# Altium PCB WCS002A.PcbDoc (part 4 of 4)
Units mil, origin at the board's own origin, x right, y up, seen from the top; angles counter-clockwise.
Board outline 2300 x 4058 mil, 4 copper layers (TOP, GND, PWR, BOTTOM), stack 28.8 mil thick; 311 components, 217 nets, 982 pads, 644 vias.
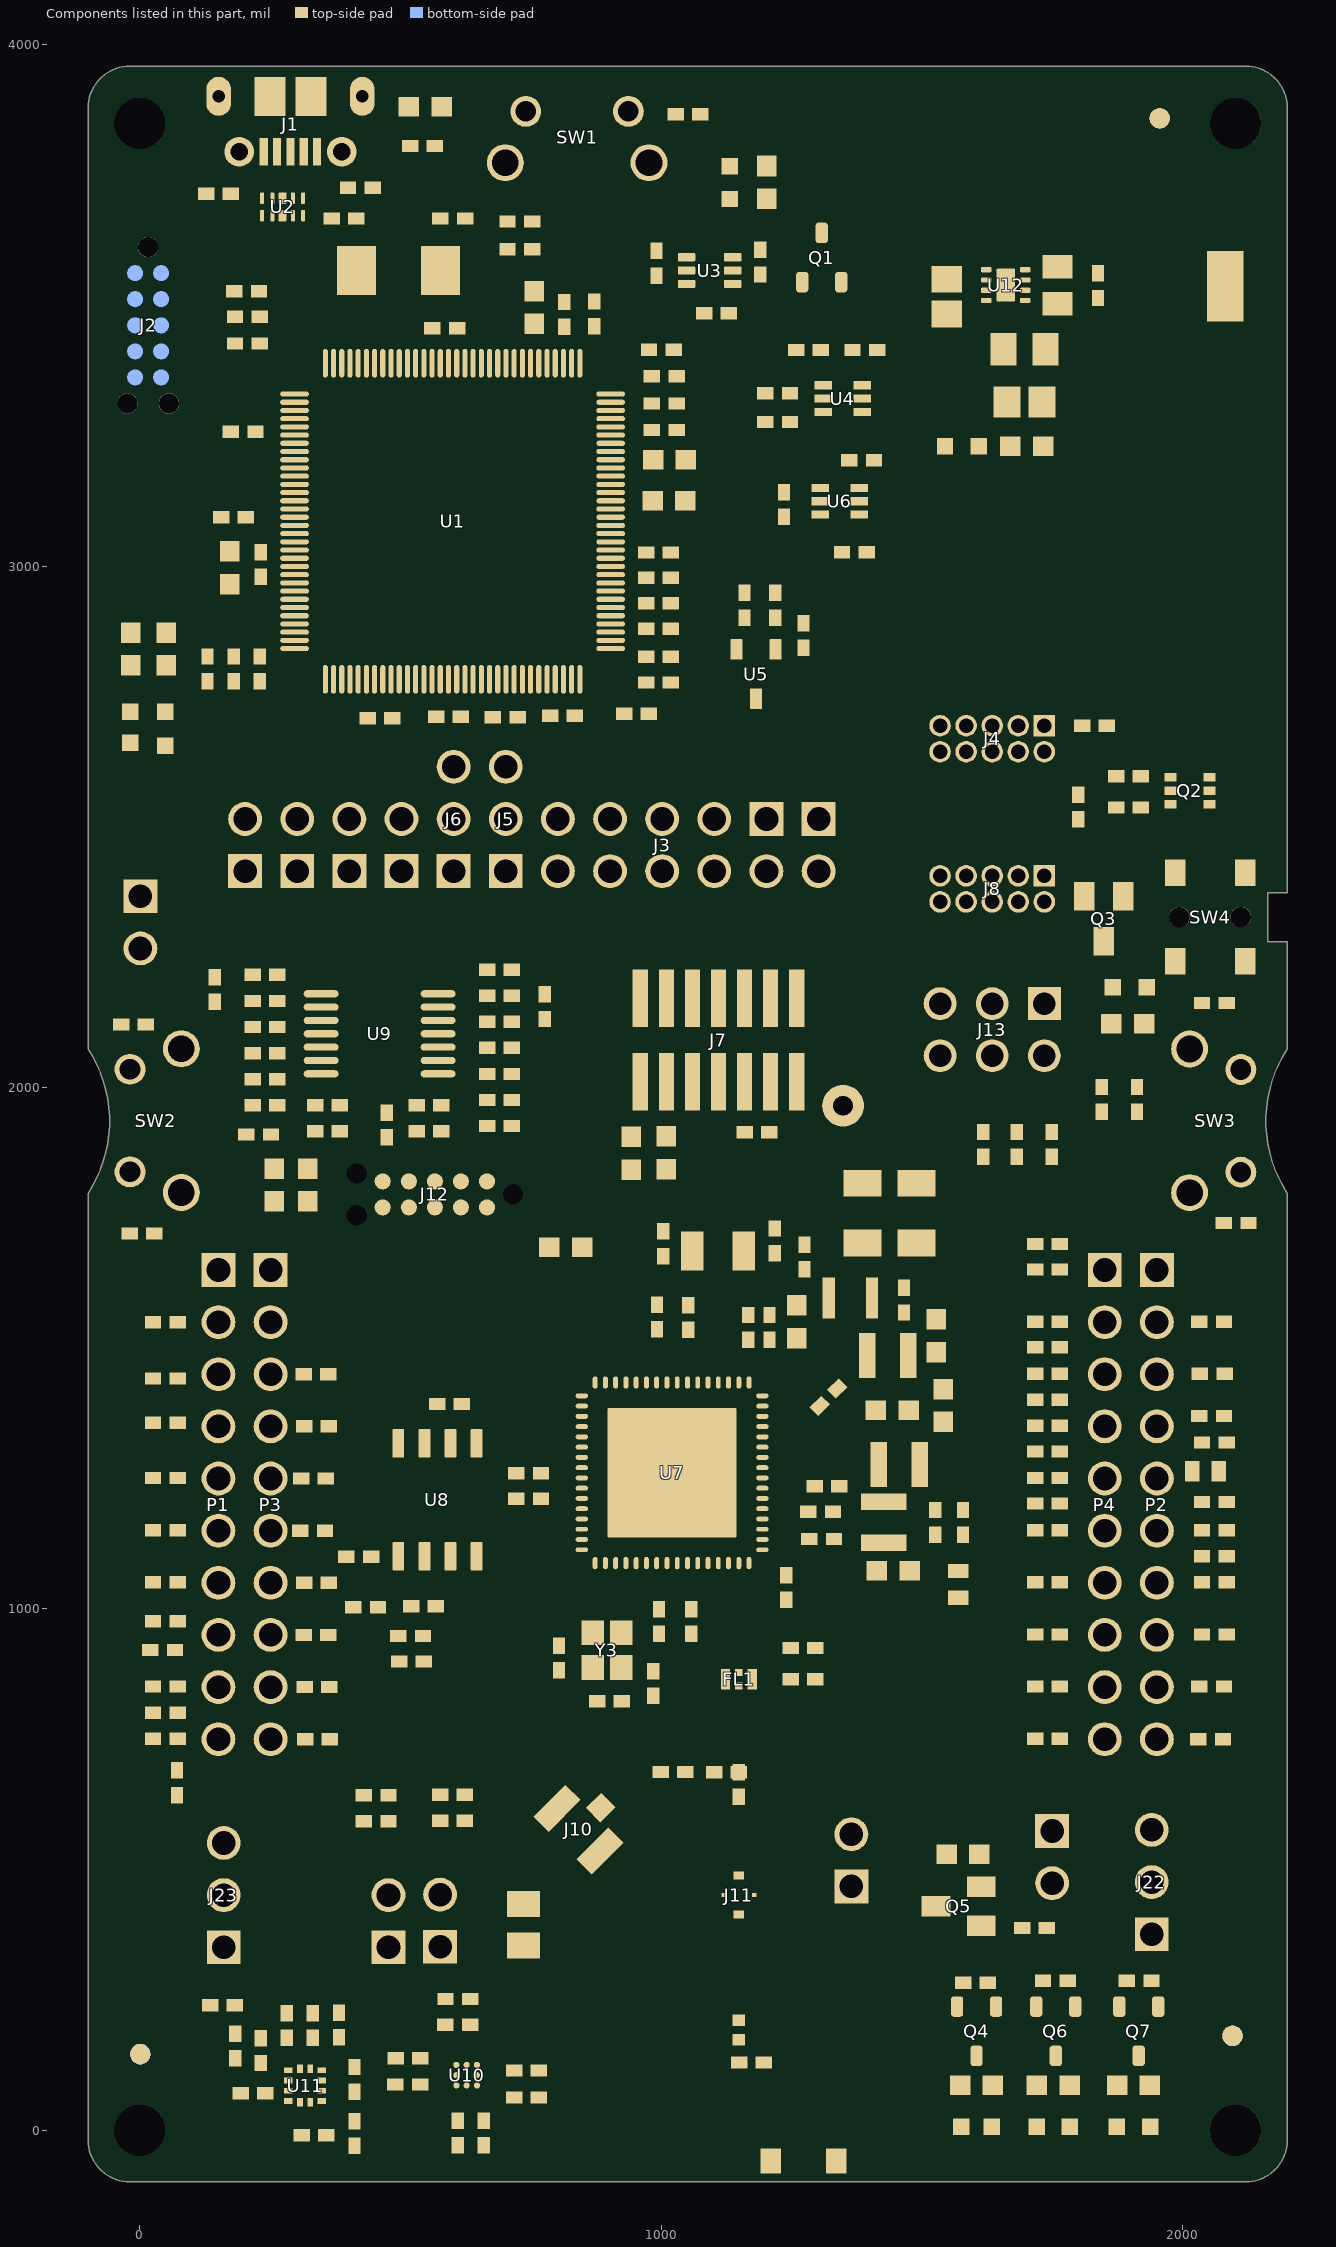
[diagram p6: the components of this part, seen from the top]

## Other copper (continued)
PWR:
  pour cut-out: 39.3,-73.7 2161.3,-73.7 2162.1,-74.5 2160.7,-74.5 2143.3,-91.9 -20.8,-91.9 -23.3,-89.4 -23.3,-87.2 -9,-72.9 -8.2,-73.7 39.24,-73.7
  pour cut-out: -75.6,1785.9 -21,1840.5 -21,2051.2 -79,2109.2 -81.8,2109.2 -91.1,2099.9 -91.1,2066.3 -64.8,2040 -64.8,1909.1 -49,1893.3 -82.21,1860.09 -82.21,1795.18 -73.7,1786.67
  pour cut-out: 2173.7,2094.5 2104.2,2025 2104.2,1823.6 2181.9,1745.9 2181.9,1805.9 2182.8,1806.8 2149,1840.6 2149,2010.3 2174,2035.3 2174,2093.8
  pour cut-out: 271,2465 271,2446 272,2445 632,2445 642.27,2455.27 634.54,2463 273,2463
  pour cut-out: -23.89,-74.21 -39.21,-74.21 -79.21,-34.21 -79.21,-5.84 -69.89,-5.84 -69.27,-10.12 -68.12,-16.12 -66.46,-21.99 -64.29,-27.7 -61.63,-33.2 -58.5,-38.44 -54.93,-43.4 -50.93,-48.02 -46.56,-52.27 -41.82,-56.13 -36.77,-59.56 -31.44,-62.54 -26.96,-64.6 -23.89,-65.88 -23.89,-74.21
  pour cut-out: 1099.37,106.14 1335.59,106.14 1335.59,-90.71 1099.37,-90.71
  pour cut-out: 1582,1506 1650,1506 1652,1504 1652,1481 1646,1475 1613,1475
  pour cut-out: 1620.4,1491.3 1620.4,1567.6 1597.79,1590.21 1597.79,1627.24 1593.32,1631.7 1572.1,1631.7 1572.1,1514.9 1595.5,1491.5 1620.3,1491.5
  pour cut-out: 109.4,1691.7 112.9,1695.2 190,1695.2 214.7,1670.5 214.7,1659.8 204.69,1649.79 113.31,1649.79 109.3,1653.8 109.4,1653.9
  pour cut-out: 709.1,2645 713.6,2640.5 725.8,2640.5 728.3,2643 728.3,2666.52 724.03,2670.79 714.19,2670.79 709.1,2665.7
  pour cut-out: 696.6,1322.3 696.6,1259.1 703.5,1252.2 708.2,1252.2 723.7,1267.7 723.7,1314.3 713,1325 709.8,1321.8 696.3,1321.8
  pour cut-out: 1292.69,3147.2 1291.14,3155 1286.72,3161.62 1280.1,3166.04 1272.3,3167.59 1264.5,3166.04 1257.88,3161.62 1253.46,3155 1251.91,3147.2 1253.46,3139.4 1257.88,3132.78 1264.5,3128.36 1272.3,3126.81 1280.1,3128.36 1286.72,3132.78 1291.14,3139.4 1292.69,3147.2
  pour cut-out: 381.29,3048.9 379.74,3056.7 375.32,3063.32 368.7,3067.74 360.9,3069.29 353.1,3067.74 346.48,3063.32 342.06,3056.7 340.51,3048.9 342.06,3041.09 346.48,3034.48 353.1,3030.06 360.9,3028.5 368.7,3030.06 375.32,3034.48 379.74,3041.09 381.29,3048.9
  pour cut-out: 1670.62,3576.07 1669.06,3583.87 1664.64,3590.49 1658.03,3594.91 1650.22,3596.46 1642.42,3594.91 1635.8,3590.49 1631.38,3583.87 1629.83,3576.07 1631.38,3568.27 1635.8,3561.65 1642.42,3557.23 1650.22,3555.68 1658.03,3557.23 1664.64,3561.65 1669.06,3568.27 1670.62,3576.07
  pour cut-out: 1683.39,3575.2 1681.84,3583 1677.42,3589.62 1670.8,3594.04 1663,3595.59 1655.2,3594.04 1648.58,3589.62 1644.16,3583 1642.61,3575.2 1644.16,3567.4 1648.58,3560.78 1655.2,3556.36 1663,3554.81 1670.8,3556.36 1677.42,3560.78 1681.84,3567.4 1683.39,3575.2
  pour cut-out: 711.58,678.76 710.03,686.56 705.61,693.18 699,697.6 691.19,699.15 683.39,697.6 676.77,693.18 672.35,686.56 670.8,678.76 672.35,670.96 676.77,664.34 683.39,659.92 691.19,658.37 699,659.92 705.61,664.34 710.03,670.96 711.58,678.76
  pour cut-out: 634.93,1221.66 633.38,1229.46 628.96,1236.08 622.34,1240.5 614.54,1242.05 606.74,1240.5 600.12,1236.08 595.7,1229.46 594.15,1221.66 595.7,1213.86 600.12,1207.24 606.74,1202.82 614.54,1201.27 622.34,1202.82 628.96,1207.24 633.38,1213.86 634.93,1221.66
  pour cut-out: 434.18,1696.79 432.63,1704.59 428.21,1711.21 421.59,1715.63 413.79,1717.18 405.98,1715.63 399.37,1711.21 394.95,1704.59 393.4,1696.79 394.95,1688.98 399.37,1682.37 405.98,1677.95 413.79,1676.4 421.59,1677.95 428.21,1682.37 432.63,1688.98 434.18,1696.79
  pour cut-out: 649.17,1696.79 647.62,1704.59 643.2,1711.21 636.58,1715.63 628.78,1717.18 620.98,1715.63 614.36,1711.21 609.94,1704.59 608.39,1696.79 609.94,1688.98 614.36,1682.37 620.98,1677.95 628.78,1676.4 636.58,1677.95 643.2,1682.37 647.62,1688.98 649.17,1696.79
  pour cut-out: 438.79,1709.9 437.24,1717.7 432.82,1724.32 426.2,1728.74 418.4,1730.29 410.6,1728.74 403.98,1724.32 399.56,1717.7 398.01,1709.9 399.56,1702.1 403.98,1695.48 410.6,1691.06 418.4,1689.51 426.2,1691.06 432.82,1695.48 437.24,1702.1 438.79,1709.9
  pour cut-out: 1006.18,1640.61 1004.63,1648.42 1000.21,1655.03 993.59,1659.45 985.79,1661.01 977.98,1659.45 971.37,1655.03 966.95,1648.42 965.4,1640.61 966.95,1632.81 971.37,1626.19 977.98,1621.77 985.79,1620.22 993.59,1621.77 1000.21,1626.19 1004.63,1632.81 1006.18,1640.61
  pour cut-out: 1235.59,1619.9 1234.04,1627.7 1229.62,1634.32 1223,1638.74 1215.2,1640.29 1207.4,1638.74 1200.78,1634.32 1196.36,1627.7 1194.81,1619.9 1196.36,1612.1 1200.78,1605.48 1207.4,1601.06 1215.2,1599.51 1223,1601.06 1229.62,1605.48 1234.04,1612.1 1235.59,1619.9
  pour cut-out: 1246.7,1603.27 1245.15,1611.07 1240.73,1617.69 1234.12,1622.11 1226.31,1623.66 1218.51,1622.11 1211.89,1617.69 1207.47,1611.07 1205.92,1603.27 1207.47,1595.47 1211.89,1588.85 1218.51,1584.43 1226.31,1582.88 1234.12,1584.43 1240.73,1588.85 1245.15,1595.47 1246.7,1603.27
  pour cut-out: 1381,1136.01 1379.45,1143.81 1375.03,1150.43 1368.41,1154.85 1360.61,1156.4 1352.8,1154.85 1346.19,1150.43 1341.77,1143.81 1340.22,1136.01 1341.77,1128.21 1346.19,1121.59 1352.8,1117.17 1360.61,1115.62 1368.41,1117.17 1375.03,1121.59 1379.45,1128.21 1381,1136.01
  pour cut-out: 1166.88,1594.79 1165.33,1602.59 1160.91,1609.21 1154.3,1613.63 1146.49,1615.18 1138.69,1613.63 1132.07,1609.21 1127.65,1602.59 1126.1,1594.79 1127.65,1586.99 1132.07,1580.37 1138.69,1575.95 1146.49,1574.4 1154.3,1575.95 1160.91,1580.37 1165.33,1586.99 1166.88,1594.79
  text ".layer_Name" at -459.21,-1181.21 h60
BOTTOM:
  pour cut-out: 39.3,-73.7 2161.3,-73.7 2162.1,-74.5 2160.7,-74.5 2143.3,-91.9 -20.8,-91.9 -23.3,-89.4 -23.3,-87.2 -9,-72.9 -8.2,-73.7 39.24,-73.7
  pour cut-out: 2173.7,2094.5 2104.2,2025 2104.2,1823.6 2181.9,1745.9 2181.9,1805.9 2182.8,1806.8 2149,1840.6 2149,2010.3 2174,2035.3 2174,2093.8
  pour cut-out: -75.6,1785.9 -21,1840.5 -21,2051.2 -79,2109.2 -81.8,2109.2 -91.1,2099.9 -91.1,2066.3 -64.8,2040 -64.8,1909.1 -49,1893.3 -82.21,1860.09 -82.21,1795.18 -73.7,1786.67
  pour cut-out: 1603,3528 1603,3468 1599,3464 1588,3464 1581,3471 1581,3493 1597,3509 1595,3511 1595,3521 1596,3521
  pour cut-out: 869,3482 927.16,3423.84 927.16,3411.09 928,3411.93 928,3450 896,3482
  pour cut-out: 1088.49,3311.38 1086.94,3319.19 1082.52,3325.8 1075.9,3330.22 1068.1,3331.78 1060.29,3330.22 1053.68,3325.8 1049.26,3319.19 1047.71,3311.38 1049.26,3303.58 1053.68,3296.96 1060.29,3292.54 1068.1,3290.99 1075.9,3292.54 1082.52,3296.96 1086.94,3303.58
  pour cut-out: 1729.79,1479.77 1729.75,1478.9 1729.64,1478.03 1729.45,1477.18 1729.18,1476.35 1728.85,1475.55 1728.45,1474.77 1727.98,1474.04 1727.45,1473.34 1726.86,1472.7 1726.22,1472.11 1725.52,1471.58 1724.79,1471.11 1724.01,1470.71 1723.21,1470.37 1722.38,1470.11 1721.52,1469.92 1720.66,1469.81 1719.79,1469.77 1718.92,1469.81 1718.05,1469.92 1717.2,1470.11 1716.37,1470.37 1715.56,1470.71 1714.79,1471.11 1714.05,1471.58 1713.36,1472.11 1712.72,1472.7 1703.63,1481.79 1696.88,1481.79 1696.88,1489.66 1699.36,1491.11 1700.6,1491.91 1701.78,1492.82 1702.87,1493.82 1703.86,1494.92 1704.76,1496.1 1705.55,1497.36 1706.23,1498.68 1706.79,1500.05 1707.23,1501.47 1707.54,1502.92 1707.73,1504.39 1707.78,1505.3 1707.84,1507.28 1712.72,1512.16 1713.36,1512.75 1714.05,1513.28 1714.79,1513.75 1715.56,1514.15 1716.37,1514.49 1717.2,1514.75 1718.05,1514.94 1718.92,1515.05 1719.79,1515.09 1720.66,1515.05 1721.52,1514.94 1722.38,1514.75 1723.21,1514.49 1724.01,1514.15 1724.79,1513.75 1725.52,1513.28 1726.21,1512.75 1726.86,1512.16 1727.45,1511.52 1727.98,1510.82 1728.45,1510.09 1728.85,1509.31 1729.18,1508.51 1729.45,1507.68 1729.64,1506.83 1729.75,1505.96 1729.79,1505.09 1729.79,1479.77
  pour cut-out: 152 vertices and 0 holes, not listed, extent 1873.24,1006.79 1928.33,1089.79
  pour cut-out: 2001.13,911.89 1987.86,911.89 1986.98,911.93 1986.12,912.04 1985.27,912.23 1984.44,912.5 1983.63,912.83 1982.86,913.23 1982.12,913.7 1981.43,914.23 1980.78,914.82 1980.2,915.46 1979.66,916.16 1979.2,916.89 1978.79,917.67 1978.46,918.47 1978.2,919.3 1978.01,920.16 1977.89,921.02 1977.86,921.89 1977.89,922.76 1978.01,923.63 1978.2,924.48 1978.46,925.31 1978.79,926.12 1979.2,926.89 1979.66,927.63 1979.97,928.04 1981.84,930.67 1983.48,933.45 1984.86,936.37 1985.99,939.39 1986.85,942.5 1987.43,945.68 1987.74,948.89 1987.76,952.12 1987.51,955.34 1986.97,958.52 1986.16,961.64 1985.08,964.69 1983.74,967.62 1982.6,969.68 1982.19,970.45 1981.84,971.25 1981.57,972.08 1981.37,972.93 1981.25,973.79 1981.2,974.66 1981.23,975.54 1981.33,976.4 1981.51,977.26 1981.76,978.09 1982.08,978.9 1982.48,979.68 1982.94,980.42 1983.46,981.12 1984.04,981.77 1984.68,982.37 1985.36,982.91 1986.09,983.39 1986.86,983.8 1987.66,984.14 1988.49,984.41 1989.34,984.61 1990.2,984.74 1991.07,984.79 1991.2,984.79 2005.34,984.79 2082.72,1062.16 2083.36,1062.75 2084.05,1063.28 2084.79,1063.75 2085.56,1064.15 2086.37,1064.49 2087.2,1064.75 2088.05,1064.94 2088.92,1065.05 2089.79,1065.09 2090.66,1065.05 2091.52,1064.94 2092.38,1064.75 2093.21,1064.49 2094.01,1064.15 2094.79,1063.75 2095.52,1063.28 2096.21,1062.75 2096.86,1062.16 2097.45,1061.52 2097.98,1060.82 2098.45,1060.09 2098.85,1059.31 2099.18,1058.51 2099.45,1057.68 2099.64,1056.83 2099.75,1055.96 2099.79,1055.09 2099.79,1010.54 2001.13,911.89
  pour cut-out: 1913.72,911.89 1887.86,911.89 1886.98,911.93 1886.12,912.04 1885.27,912.23 1884.44,912.5 1883.63,912.83 1882.86,913.23 1882.12,913.7 1881.43,914.23 1880.78,914.82 1880.2,915.46 1879.66,916.16 1879.2,916.89 1878.79,917.67 1878.46,918.47 1878.2,919.3 1878.01,920.16 1877.89,921.02 1877.86,921.89 1877.89,922.76 1878.01,923.63 1878.2,924.48 1878.46,925.31 1878.79,926.12 1879.2,926.89 1879.66,927.63 1879.97,928.04 1881.84,930.67 1883.48,933.45 1884.86,936.37 1885.99,939.39 1886.85,942.5 1887.43,945.68 1887.74,948.89 1887.76,952.12 1887.51,955.34 1886.97,958.52 1886.16,961.64 1885.08,964.69 1883.74,967.62 1882.6,969.68 1882.19,970.45 1881.84,971.25 1881.57,972.08 1881.37,972.93 1881.25,973.79 1881.2,974.66 1881.23,975.54 1881.33,976.4 1881.51,977.26 1881.76,978.09 1882.08,978.9 1882.48,979.68 1882.94,980.42 1883.46,981.12 1884.04,981.77 1884.68,982.37 1885.36,982.91 1886.09,983.39 1886.86,983.8 1887.66,984.14 1888.49,984.41 1889.34,984.61 1890.2,984.74 1891.07,984.79 1891.2,984.79 1910.38,984.79 1911.25,984.75 1912.11,984.64 1912.96,984.45 1913.8,984.18 1914.6,983.85 1915.38,983.45 1916.11,982.98 1916.8,982.45 1917.45,981.86 1918.04,981.22 1918.57,980.52 1919.04,979.79 1919.44,979.01 1919.77,978.21 1920.04,977.38 1920.22,976.52 1920.34,975.66 1920.38,974.79 1920.34,973.92 1920.22,973.05 1920.04,972.2 1919.77,971.37 1919.44,970.56 1919.04,969.79 1918.97,969.68 1917.45,966.84 1916.18,963.87 1915.17,960.8 1914.43,957.66 1913.97,954.47 1913.79,951.24 1913.89,948.02 1914.27,944.81 1914.93,941.65 1915.87,938.56 1917.06,935.56 1918.52,932.68 1920.22,929.94 1921.61,928.04 1922.11,927.33 1922.55,926.58 1922.93,925.79 1923.23,924.97 1923.46,924.13 1923.62,923.27 1923.71,922.4 1923.71,921.53 1923.64,920.66 1923.5,919.8 1923.28,918.96 1922.99,918.14 1922.62,917.34 1922.19,916.58 1921.7,915.87 1921.14,915.19 1920.53,914.57 1919.87,914.01 1919.16,913.5 1918.4,913.06 1917.62,912.68 1916.8,912.38 1915.96,912.15 1915.1,911.99 1914.23,911.91 1913.72,911.89
  pour cut-out: 1451.44,1729.57 1452.03,1728.93 1452.57,1728.24 1453.03,1727.5 1453.44,1726.73 1453.77,1725.92 1454.03,1725.09 1454.22,1724.24 1454.34,1723.37 1454.37,1722.5 1454.34,1721.63 1454.22,1720.77 1454.03,1719.91 1453.77,1719.08 1453.44,1718.28 1453.03,1717.5 1452.57,1716.77 1452.03,1716.07 1451.44,1715.43 1450.8,1714.84 1450.11,1714.31 1449.37,1713.84 1448.6,1713.44 1447.79,1713.11 1446.96,1712.84 1446.11,1712.65 1445.25,1712.54 1444.37,1712.5 862.2,1712.5 861.33,1712.54 860.46,1712.65 859.61,1712.84 858.78,1713.11 857.97,1713.44 857.2,1713.84 856.47,1714.31 855.77,1714.84 855.13,1715.43 854.54,1716.07 854.01,1716.77 853.54,1717.5 853.14,1718.28 852.8,1719.08 852.54,1719.91 852.35,1720.77 852.24,1721.63 852.2,1722.5 852.24,1723.37 852.35,1724.24 852.54,1725.09 852.8,1725.92 853.14,1726.73 853.54,1727.5 854.01,1728.24 854.54,1728.93 855.13,1729.57 860.34,1734.79 1446.23,1734.79 1451.44,1729.57
  pour cut-out: 1596.23,816.79 1208.52,816.79 1207.65,816.83 1206.78,816.94 1205.93,817.13 1205.1,817.39 1204.29,817.72 1203.52,818.13 1202.79,818.6 1202.09,819.13 1201.45,819.72 1200.86,820.36 1200.33,821.05 1199.86,821.79 1199.46,822.56 1199.12,823.37 1198.86,824.2 1198.67,825.05 1198.56,825.92 1198.52,826.79 1198.56,827.66 1198.67,828.52 1198.71,828.73 1198.94,830.2 1199.03,831.68 1199.03,831.75 1199.09,832.62 1199.21,833.48 1199.42,834.33 1199.69,835.16 1200.04,835.96 1200.46,836.73 1200.94,837.46 1201.48,838.14 1202.08,838.77 1202.73,839.35 1203.44,839.87 1204.18,840.33 1204.96,840.72 1205.77,841.04 1206.61,841.28 1207.46,841.46 1208.33,841.56 1209.03,841.58 1596.88,841.58 1597.76,841.54 1598.62,841.43 1599.47,841.24 1600.3,840.98 1601.11,840.65 1601.88,840.24 1602.62,839.77 1603.31,839.24 1603.95,838.65 1604.54,838.01 1605.08,837.32 1605.54,836.58 1605.95,835.81 1606.28,835 1606.54,834.17 1606.73,833.32 1606.85,832.45 1606.88,831.58 1606.85,830.71 1606.73,829.85 1606.54,828.99 1606.28,828.16 1605.95,827.36 1605.54,826.58 1605.08,825.85 1604.54,825.15 1603.95,824.51 1596.23,816.79
  pour cut-out: 935.79,741.79 1137.04,741.79 1163.04,767.79 1125.04,805.79 926.79,805.79 909.79,788.79 935.79,762.79
  pour cut-out: 1380.76,1134.37 1379.21,1142.17 1374.79,1148.79 1368.17,1153.21 1360.37,1154.76 1352.56,1153.21 1345.95,1148.79 1341.53,1142.17 1339.98,1134.37 1341.53,1126.56 1345.95,1119.95 1352.56,1115.53 1360.37,1113.98 1368.17,1115.53 1374.79,1119.95 1379.21,1126.56 1380.76,1134.37
  pour cut-out: 1398.18,1249.79 1396.63,1257.59 1392.21,1264.21 1385.59,1268.63 1377.79,1270.18 1369.98,1268.63 1363.37,1264.21 1358.95,1257.59 1357.4,1249.79 1358.95,1241.98 1363.37,1235.37 1369.98,1230.95 1377.79,1229.4 1385.59,1230.95 1392.21,1235.37 1396.63,1241.98
  pour cut-out: 1381.55,1187.68 1380,1195.48 1375.58,1202.1 1368.96,1206.52 1361.16,1208.07 1353.35,1206.52 1346.74,1202.1 1342.32,1195.48 1340.77,1187.68 1342.32,1179.87 1346.74,1173.26 1353.35,1168.84 1361.16,1167.28 1368.96,1168.84 1375.58,1173.26 1380,1179.87
  pour cut-out: 596.79,1359.79 596.79,1537.79 809.79,1750.79 1575.79,1750.79 1646.79,1679.79 1646.79,1550.79 1616.79,1520.79 823.79,1520.79 661.79,1358.79 594.79,1358.79
  pour cut-out: 732.79,786.79 1627.79,786.79 1633.79,792.79 1633.79,1108.79 1604.79,1137.79 1271.08,1137.79 1172.67,1039.38 835.19,1039.38 770.79,1103.79 770.79,1227.79 674.79,1323.79 482.79,1323.79 454.79,1295.79 454.79,1054.79 456.79,1052.79 562.79,1052.79 665.79,949.79 665.79,853.79
  pour cut-out: 1211.55,767.68 1210,775.48 1205.58,782.1 1198.96,786.52 1191.16,788.07 1183.35,786.52 1176.74,782.1 1172.32,775.48 1170.77,767.68 1172.32,759.87 1176.74,753.26 1183.35,748.84 1191.16,747.28 1198.96,748.84 1205.58,753.26 1210,759.87 1211.55,767.68
  pour cut-out: 1129.42,726.68 1127.87,734.48 1123.45,741.1 1116.83,745.52 1109.03,747.07 1101.23,745.52 1094.61,741.1 1090.19,734.48 1088.64,726.68 1090.19,718.87 1094.61,712.26 1101.23,707.84 1109.03,706.28 1116.83,707.84 1123.45,712.26 1127.87,718.87 1129.42,726.68
  pour cut-out: 1079.42,727.68 1077.87,735.48 1073.45,742.1 1066.83,746.52 1059.03,748.07 1051.23,746.52 1044.61,742.1 1040.19,735.48 1038.64,727.68 1040.19,719.87 1044.61,713.26 1051.23,708.84 1059.03,707.28 1066.83,708.84 1073.45,713.26 1077.87,719.87 1079.42,727.68
  pour cut-out: 1038.42,725.68 1036.87,733.48 1032.45,740.1 1025.83,744.52 1018.03,746.07 1010.23,744.52 1003.61,740.1 999.19,733.48 997.64,725.68 999.19,717.87 1003.61,711.26 1010.23,706.84 1018.03,705.28 1025.83,706.84 1032.45,711.26 1036.87,717.87 1038.42,725.68
  pour cut-out: 1099.37,106.14 1335.59,106.14 1335.59,-90.71 1099.37,-90.71
  pour cut-out: 1005.38,1819.54 1052.04,1819.54 1055.79,1815.79 1055.79,1801.79 1038.79,1784.79 1000.79,1784.79 987.79,1797.79 987.79,1801.94
  text ".layer_Name" at -465.21,-1173.21 h60

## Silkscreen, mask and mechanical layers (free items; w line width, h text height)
DETAILS:
  drawing of 7067 lines, arcs and shapes, not listed
  text "J1" at 78.79,3878.79 h30
  text "L2" at 84,3741 h30
  text "RESET" at 1086.21,3688.79 h30 r90
  text "RESET" at 785.79,3680.79 h30
  text "U3" at 1634.7,3602.6 h30
  text "GND" at 2019,3498.71 h30 r90
  text "3V3" at 1508,3271 h30
  text "CC3220" at 1709.5,3101.9 h120
  text "CAUTION" at -77.1,3030 h30
  text "LaunchPad" at 1708.5,3014.1 h120
  text "HOT" at -22.6,2981.9 h30
  text "Rev-A" at 1707.4,2946.3 h80
  text "SURFACE" at -80.6,2939.3 h30
  text "XDS110" at 1509.1,2841.5 h30
  text "OUT" at 1512.3,2789.6 h30
  text "VSENSE" at 1315,2589 h30 r90
  text "JTAG IN" at 1524.79,2496.79 h30
  text "FRST" at 1969.2,2465.7 h30
  text "TX" at 724,2297.14 h30 r90
  text "RX" at 623,2294 h30 r90
  text "5V" at 322.4,2272.7 h30 r90
  text "BRD" at 513.79,2267.29 h30 r90
  text "RST" at 821.79,2267.29 h30 r90
  text "TMS" at 928,2268 h30 r90
  text "TCK" at 1026.79,2267.58 h30 r90
  text "TDI" at 1127.79,2267.29 h30 r90
  text "BRD" at 1322.79,2267.29 h30 r90
  text "TDO" at 1233.79,2265.72 h30 r90
  text "GND" at 221.8,2252.3 h30 r90
  text "VBAT" at 421.7,2228 h30 r90
  text "OPAMP EN" at 108.6,2209 h30 r90
  text "J13" at 1398.6,2197.8 h30
  text "SOP" at 1466.1,2060.4 h40 r90
  text "ET POD" at 916.79,1997.79 h30 r90
  text "0" at 1729.39,1997.49 h40 r180
  text "1" at 1610.39,1955.49 h40
  text "2" at 1524.39,1954.49 h40
  text "(P15)" at 1850.9,1816.8 h30
  text "(P4)" at 137.79,1772.79 h30
  text "P4" at 1797.79,1713.79 h40
  text "P2" at 1977.9,1713.8 h40
  text "P1" at 79.79,1701.79 h40
  text "P3" at 277.79,1701.79 h40
  text "1" at 157.79,1700.79 h35
  text "21" at 207.79,1700.79 h35
  text "40" at 1858.79,1691.79 h30
  text "20" at 1916.79,1691.79 h30
  text "*" at 1678.9,1655.2 h30
  text "P02" at 1606.19,1630.79 h30
  text "*" at 1671.4,1559.4 h30
  text "*" at -16.21,1549.79 h30
  text "P18" at 2107.4,1535.2 h30
  text "P01" at 1606.19,1530.79 h30
  text "P58" at -88.91,1514.19 h30
  text "U13" at 787.79,1474.79 h35
  text "*" at 1675.6,1456.8 h30
  text "P57" at 388.8,1435.3 h30
  text "P08" at 2107.5,1433.2 h30
  text "P17" at 1606.19,1430.79 h30
  text "P04" at -89.21,1428.79 h30
  text "*" at 1674.2,1354.5 h30
  text "P45" at 2106.1,1348.7 h30
  text "P60" at 390.9,1341.1 h30
  text "P03" at -91.1,1337.6 h30
  text "P64" at 1606.19,1329.79 h30
  text "*" at 1663.9,1271.1 h30
  text "P61" at -84.1,1241.1 h30
  text "RST" at 2109.9,1240.5 h30
  text "P58" at 386.1,1237.6 h30
  text "P21" at 1606.19,1234.79 h30
  text "*" at 1666.5,1169 h30
  text "*" at -28,1158 h30
  text "P59" at 380.2,1138.1 h30
  text "P07" at 2108.9,1136 h30
  text "P18" at 1606.19,1134.79 h30
  text "P59" at -89.2,1125.2 h30
  text "*" at 1677.8,1060.1 h30
  text "P05" at -89.21,1040.79 h30
  text "P06" at 2111.7,1035.2 h30
  text "P63" at 390.9,1033.3 h30
  text "P62" at 1608.5,1033.8 h30
  text "*" at 1666.3,967.5 h30
  text "P62" at -89.4,952.9 h30
  text "P21" at 2113.3,934.6 h30
  text "P53" at 395,932.6 h30
  text "P60" at 1606.19,932.79 h30
  text "P01" at -89.21,840.79 h30
  text "P55" at 2104.7,834.5 h30
  text "P64" at 391.9,830 h30
  text "P16" at 1606.19,827.79 h30
  text "P02" at -89.21,740.79 h30
  text "P17" at 1606.19,738.79 h30
  text "P50" at 392.8,732.4 h30
  text "P15" at 2106.5,732.9 h30
  text "30" at 227.96,667.79 h35
  text "11" at 1929.61,667.78 h35
  text "10" at 125.79,666.79 h35
  text "31" at 1827.44,666.78 h35
  text "RF" at 705.6,502 h30
  text "RF" at 1004.79,466.79 h30
  text "RST PU" at 1682.79,458.79 h30 r90
  text "LED EN" at 1283.6,449.3 h30 r90
  text "Q2" at 1434.6,356.2 h30
  text "(SCL)" at 389.79,325.79 h30 r90
  text "(SDA)" at 671.79,313.79 h30 r90
  text "D8->P02" at 1279.7,246.4 h30
  text "Q5" at 2019,208.9 h30 r90
  text "D9->P01" at 1279.79,194.79 h30
  text "Q4" at 1850.79,194.79 h30 r90
  text "Q3" at 1543.79,192.79 h30 r90
  text "TEMP" at 671.79,153.79 h30
  text "D10->P64" at 1277.79,143.79 h30
  text "SENSORS" at 121.79,-6.21 h30 r90
  text "ACC" at 152.79,-63.21 h30
  text "SILKSCREEN TOP" at -415.75,-1159.26 h60
QRCODE:
  drawing of 11592 lines, arcs and shapes, not listed
  text "CC3220x-LAUNCHXL" at 1252,3290.5 h125
  text "Development Kit" at 1248.2,3176.8 h125
  text "www.ti.com/launchpad" at 1579.5,2925.2 h125
  text "XDS110 OUT" at 1804.9,2733.8 h70
  text "VSENSE" at 1289,2579 h50 r270
  text "JTAG IN" at 1755,2457 h70
  text "OPAMP EN" at 72.8,2226 h50 r270
  text "GND" at 144.5,2224.5 h50 r270
  text "BRD" at 449.2,2224.9 h50 r270
  text "RX" at 549.3,2224.7 h50 r270
  text "TX" at 649.4,2224.7 h50 r270
  text "TCK" at 952.9,2224.4 h50 r270
  text "TDI" at 1051.1,2225.1 h50 r270
  text "TDO" at 1149.8,2224.5 h50 r270
  text "5V" at 249.6,2223.8 h50 r270
  text "VBAT" at 349,2224.1 h50 r270
  text "RST" at 753.1,2224.1 h50 r270
  text "TMS" at 851.8,2223.6 h50 r270
  text "BRD" at 1252.9,2224 h50 r270
  text "SOP" at 1710.2,2214.32 h70
  text "SOP (2:0)" at 1178.4,2005.6 h40
  text "100  :  FLASH" at 1176.4,1945.6 h30
  text "000  :  4W JTAG" at 1175.4,1886.6 h30
  text "001  :  2W SWD" at 1178.4,1833.6 h30
  text "010  :  FLASH/FUNC" at 1176.4,1781.6 h30
  text "1" at 167,1728 h35
  text "21" at 266,1728 h35
  text "40" at 1878,1728 h35
  text "20" at 1969,1728 h35
  text "P02(NC)" at 1777.79,1632.79 h35
  text "P18" at 2102.79,1537.79 h35
  text "P01(NC)" at 1777.79,1532.79 h35
  text "P58(NC)" at 86.1,1530.4 h31
  text "P08" at 2105.79,1435.79 h35
  text "P57" at 403.8,1432.4 h35
  text "P17(NC)" at 1777.79,1432.79 h35
  text "P04" at 80,1427.79 h35
  text "P60" at 400,1341.7 h35
  text "P45" at 2106.79,1334.79 h35
  text "P64(NC)" at 1777.79,1331.79 h35
  text "P03" at 80,1327.79 h35
  text "P58" at 401.5,1244.1 h35
  text "P21(NC)" at 1777.79,1234.79 h35
  text "RST" at 2099.79,1234.79 h35
  text "P61" at 80,1227.79 h35
  text "P07" at 2103.7,1137.4 h35
  text "P59" at 400,1133.5 h35
  text "P18(NC)" at 1777.79,1133.79 h35
  text "P59(NC)" at 86.2,1128.1 h33
  text "P62(NC)" at 1777.79,1037.79 h35
  text "P06" at 2096.79,1036.79 h35
  text "P05" at 80,1027.79 h35
  text "P63" at 399.2,1026 h35
  text "P21" at 2100.79,934.79 h35
  text "P60(NC)" at 1777.79,933.79 h35
  text "P62" at 80,927.79 h35
  text "P53" at 405.1,919.8 h35
  text "P64" at 404.9,835.8 h35
  text "P55" at 2100.79,834.79 h35
  text "P16(NC)" at 1777.79,830.79 h35
  text "P01" at 80,827.79 h35
  text "P50" at 399.7,735.8 h35
  text "P15" at 2100.79,734.79 h35
  text "P17(NC)" at 1777,734 h35
  text "P02" at 80,727.79 h35
  text "30" at 272.39,635.79 h35
  text "11" at 1963.2,635.8 h35
  text "31" at 1869.3,635 h35
  text "10" at 166.39,633.79 h35
  text "LED EN" at 1251.7,450.6 h30 r270
  text "WCS002A" at 1032.9,249.3 h50
  text "not FCC approved for resale." at 1034.19,84.19 h40
  text "SILKSCREEN BOTTOM" at -415.75,-1159.26 h60
Top Paste:
  text ".layer_Name" at -406.21,-1149.21 h60
Bottom Paste:
  text ".layer_Name" at -446.21,-1143.21 h60
Top Solder:
  region: 1131.07,438.19 1122.02,429.13 1103.51,429.13 1103.51,472.44 1122.02,472.44 1131.07,463.39
  region: 1166.5,463.39 1175.56,472.44 1194.06,472.44 1194.06,429.13 1175.56,429.13 1166.5,438.19
  text ".layer_Name" at -415.21,-1139.21 h60
Bottom Solder:
  text ".layer_Name" at -403.21,-1146.21 h60
M1  Board Outline:
  the board outline again, w10
M2 Board Dimensions:
  drawing of 35 lines, arcs and shapes, not listed
  text "2 PLACES" at -655.21,1985 h60
  text "4 PLACES" at 1480.79,-337 h60
M3 3D STEP Top:
  pour cut-out: 1580.79,1720.79 1580.79,960.79 1155.79,960.79 1155.79,990.79 1120.79,1025.79 1035.79,1025.79 1000.79,990.79 1000.79,910.79 935.79,910.79 935.79,805.79 925.79,795.79 655.79,795.79 655.79,1720.79 1580.79,1720.79
AST:
  circle w6: c1362.2,399 r7.21
  circle w6: c1.7,2440.1 r7.21
  circle w10: c1236.6,3528.4 r8.25
  circle w10: c993.8,3910.8 r4
  circle w10: c2112.8,1779.6 r4
  circle w10: c-10.3,2086.6 r4
  circle w6: c407.49,299.59 r10
  circle w6: c642.69,302.79 r10
  circle w10: c1942.2,2450.2 r8.06
  circle w6: c78.79,346.79 r10
  circle w6: c1690.79,311.79 r7.21
  circle w6: c1074.32,1668.79 r4.47
  circle w6: c341.79,3736.79 r7.21
  circle w6: c205,2339 r7.21
  circle w6: c305,2339 r7.21
  circle w6: c405,2339 r7.21
  circle w6: c505,2339 r7.21
  circle w6: c605,2339 r7.21
  circle w6: c705,2339 r7.21
  circle w6: c1204,2596 r7.21
  circle w6: c1302,2597 r7.21
  circle w6: c1304,2190 r7.21
  circle w6: c1752.4,2467.5 r7.21
  circle w6: c1772,2754 r7.21
  circle w6: c1670,241 r7.21
  circle w6: c1826,242 r7.21
  circle w6: c1987,242 r7.21
  circle w6: c1623,346 r7.21
  circle w6: c1819,590 r7.21
  circle w10: c1219.19,2798.39 r8.06
  circle w6: c1074.32,1668.79 r4.47
  circle w6: c879.2,671.8 r6.71
  circle w6: c1869,379 r7.21
  circle w6: c78.79,346.79 r10
  circle w10: c352,3588 r8.25
  circle w10: c1958.7,2632.2 r8.06
  lines w10: -1273.71,-1222.38 5326.29,-1222.38 ; -1273.71,-1019.05 5328.29,-1019.05 ; -1273.71,-815.71 -1273.71,-1425.71 2731.29,-1425.71 5328.29,-1425.71 5328.29,-815.71 -1273.21,-815.71 -1273.21,-1425.71 302.29,-1425.71 ; 1191.29,-1425.71 1191.29,-815.71 ; 1893.38,2422.16 ccw(c1886.1,2418.7) 1894.16,2418.7 ; 2458.29,-1019.05 2458.29,-815.71 ; 3298.29,-1019.05 3298.29,-815.71 ; 3920.29,-1432.21 3920.29,-1229.38
  text "J1" at 264.7,3857.6 h30
  text "L2" at 130.7,3702.1 h24
  text "J15" at 1594.5,2096.7 h30
  text "J25" at 511.8,1776.3 h30
  text "REFER SPECIAL" at 353.5,1686.5 h30
  text "ASSEMBLY NOTE" at 324.3,1633.8 h30
  text "Special Assembly Note: Please provide a insulating tape on the J25 (DNP) pads to avoid the paste and led on them while soldering the other parts." at 176.79,-493.91 h35
  text "COMPONENTS MARKED 'DNP' SHOULD NOT BE POPULATED." at 171.79,-610.71 h35
  text "ASSEMBLY VARIANT:" at 171.29,-726.21 h35
  text ".VariantName" at 1207.29,-726.21 h35
  text "PCB VIEWED FROM TOP SIDE" at -1210.21,-947.88 h35
  text "BOARD #:" at 1266.29,-947.88 h35
  text ".PRJ_Number" at 1811.79,-947.88 h35
  text "REV:" at 2656.29,-947.88 h35
  text ".PCB_Rev" at 2947.79,-947.88 h35
  text "SVN REV:" at 3494.29,-947.88 h35
  text ".VersionControl_RevNumber" at 4000.29,-947.88 h35
  text "IGNORE ->" at -1210.21,-1150.71 h35
  text ".Layer_Name" at -427.71,-1150.21 h35
  text "PLOT NAME =" at -1210.21,-1356.55 h35
  text ".plot_File_Name" at -404.71,-1356.55 h35
  text "GENERATED    :" at 1268.29,-1356.55 h35
  text ".Print_Date" at 2137.79,-1356.55 h35
  text ".Print_Time" at 2866.79,-1356.55 h35
  text "TEXAS INSTRUMENTS" at 4131.29,-1356.55 h35
ASB:
  lines w10: -1274.21,-1019.55 5327.79,-1019.55 ; -1272.21,-1222.88 5327.79,-1222.88 ; 133.79,-1432.71 133.79,-1229.88 ; 755.79,-1019.55 755.79,-816.21 ; 1595.79,-1019.55 1595.79,-816.21 ; 2862.79,-1426.21 2862.79,-816.21 ; 3751.79,-1426.21 5327.29,-1426.21 5327.29,-816.21 -1274.21,-816.21 -1274.21,-1426.21 1322.79,-1426.21 5327.79,-1426.21 5327.79,-816.21
  text "COMPONENTS MARKED 'DNP' SHOULD NOT BE POPULATED." at 5120.29,-610.21 h35
  text ".VariantName" at 4076.29,-726.21 h35
  text "ASSEMBLY VARIANT:" at 5115.29,-726.21 h35
  text ".VersionControl_RevNumber" at 53.79,-948.38 h35
  text "SVN REV:" at 559.79,-948.38 h35
  text ".PCB_Rev" at 1106.29,-948.38 h35
  text "REV:" at 1397.79,-948.38 h35
  text ".PRJ_Number" at 2242.29,-948.38 h35
  text "BOARD #:" at 2787.79,-948.38 h35
  text "PCB VIEWED FROM BOTTOM SIDE" at 5264.29,-948.38 h35
  text "IGNORE ->" at 1566.14,-1150.71 h35
  text ".Layer_Name" at 1226.79,-1153.21 h35
  text "TEXAS INSTRUMENTS" at -77.21,-1357.05 h35
  text ".Print_Time" at 1187.29,-1357.05 h35
  text ".Print_Date" at 1916.29,-1357.05 h35
  text "GENERATED    :" at 2785.79,-1357.05 h35
  text ".plot_File_Name" at 4458.79,-1357.05 h35
  text "PLOT NAME =" at 5264.29,-1357.05 h35
M9 Title Sheet:
  drawing of 56 lines, arcs and shapes, not listed
  text "1" at -252.91,7735.73 h70
  text "2" at 2242.75,7735.73 h70
  text "3" at 4732.1,7735.73 h70
  text "4" at 7238.77,7735.73 h70
  text "5" at 9737.75,7735.73 h70
  text "6" at 12242.75,7735.73 h70
  text "A" at -1409.25,6592.73 h70
  text "A" at 13390.75,6592.73 h70
  text "B" at -1409.25,4212.73 h70
  text "B" at 13390.75,4212.73 h70
  text "C" at -1409.25,1837.73 h70
  text "C" at 13390.75,1837.73 h70
  text "PROJECT TITLE:" at 10350.75,-23.27 h45
  text ".PRJ_Title" at 10400.75,-156.6 h70
  text "DESIGNED FOR:" at 10350.75,-324.27 h45
  text ".PRJ_Customer" at 10400.75,-464.27 h70
  text "D" at -1409.25,-532.27 h70
  text "D" at 13390.75,-532.27 h70
  text "FILE NAME:" at 10350.75,-624.27 h45
  text ".PCB_File_Name_No_Path" at 10400.75,-744.27 h70
  text "Texas Instruments (TI) and/or its licensors do not warrant the accuracy or completeness of this specification" at 5381.25,-906.11 h45
  text "ENGINEER:" at 10350.75,-914.27 h45
  text "LAYOUT BY:" at 11855.75,-914.27 h45
  text "or any information contained therein. TI and/or its licensors do not warrant that this design will meet" at 5336.27,-1018.77 h45
  text ".PRJ_Engineer" at 10400.75,-1069.26 h70
  text ".PCB_Layout" at 11906.25,-1069.26 h70
  text "the specifications, will be suitable for your application or fit for any particular purpose, or will operate in" at 5336.27,-1131.44 h45
  text "ALTIUM DESIGNER VERSION:" at 11855.75,-1224.27 h45
  text "an implementation. TI and/or its licensors do not warrant that the design is production worthy. You should" at 5336.27,-1244.1 h45
  text "completely validate and test your design implementation to confirm the system functionality for your application." at 5381.25,-1356.77 h45
  text ".print_Scale" at 10400.75,-1357.6 h70
  text ".Application_BuildNumber" at 11906.25,-1357.6 h70
  text "1" at -252.91,-1564.27 h70
  text "2" at 2242.75,-1564.27 h70
  text "3" at 4732.1,-1564.27 h70
  text "4" at 7238.77,-1564.27 h70
  text "5" at 9737.75,-1564.27 h70
  text "6" at 12242.75,-1564.27 h70
M10 Fab Notes:
  drawing of 201 lines, arcs and shapes, not listed
  text "DESIGN INFORMATION" at 11388.27,6144.23 h60
  text "MIN. TRACK WIDTH:" at 10743.71,5964.23 h60
  text "MIL" at 11994.71,5964.23 h60
  text "6" at 11835.79,5962.79 h60
  text "MIN. CLEARANCE:" at 10743.71,5832.23 h60
  text "MIL" at 11994.71,5832.23 h60
  text "5.9" at 11777.79,5820.79 h60
  text "MIN. VIA PAD SIZE:" at 10743.71,5700.23 h60
  text "18" at 11809.97,5700.23 h60
  text "MIL" at 11994.71,5700.23 h60
  text "EXTERNAL" at 12289,5560 h60
  text "0.10668mm (4.2MIL)" at 11438.71,5558.52 h60
  text "MINIMUM ANNULAR RING" at 10414.48,5554.23 h60
  text "PER" at 10614.48,5436.23 h60
  text "IPC-D-275 CLASS 2 LEVEL C" at 10834.48,5436.23 h60
  text "MIL, HOLES" at 12322.71,5323.94 h60
  text "+/-" at 11930.25,5323.23 h60
  text "+/-" at 12784.25,5323.23 h60
  text "REGISTRATION TOLERANCES:" at 10414.48,5318.23 h60
  text "METAL" at 11614.25,5318.23 h60
  text "5" at 12190.46,5318.23 h60
  text "3" at 13023.46,5318.23 h60
  text "MIL" at 13139.71,5318.23 h60
  text "MATERIAL:" at 10339.71,5108.77 h60
  text "FR-4 High Tg" at 11326.16,4968.44 h60
  text "FR-408" at 10760.72,4959.87 h60
  text "X" at 11172.71,4959.87 h60
  text "OTHER" at 12248.71,4959.87 h60
  text "1.4mm+/-10%" at 12612.25,4799.23 h60
  text "62 MIL (1.6mm) +/-10%" at 11080.82,4797.15 h60
  text "THICKNESS:" at 10414.48,4792.87 h60
  text "X" at 12247.65,4792.87 h60
  text "OTHER" at 12345.71,4792.87 h60
  text "TOLERANCE:" at 10414.48,4634.87 h60
  text "X" at 11253.79,4634.87 h60
  text "ANSI IPC-6012 TYPE 3 CLASS 2" at 11440.73,4634.87 h60
  text "OTHER +/-" at 11440.71,4478.87 h60
  text "BOW & TWIST:" at 10414.48,4321.87 h60
  text "X" at 11253.79,4321.87 h60
  text "ANSI IPC-6012 TYPE 3 CLASS 2" at 11440.73,4321.87 h60
  text "OTHER +/-" at 11440.71,4163.36 h60
  text "COPPER THICKNESS (FINISHED):" at 10393.25,3906.93 h60
  text "1.4MIL (1oz)" at 12645.25,3759.21 h60
  text "INNER SIGNAL:" at 11833.17,3754.93 h60
  text "X" at 12518.21,3754.93 h60
  text "1.4MIL (1oz)" at 11273.25,3754.21 h60
  text "OUTER:" at 10750.25,3749.93 h60
  text "X" at 11144.79,3749.29 h60
  text "DRILLING:" at 10339.71,3489.87 h60
  text "REFERENCE:" at 10414.48,3372.87 h60
  text "X" at 11062.71,3372.87 h60
  text "AS SHOWN" at 11249.71,3372.87 h60
  text "X" at 11963.71,3372.87 h60
  text "NC_DRILL FILES" at 12100.71,3372.87 h60
  text "PTH MIN COPPER THICKNESS:" at 10414.48,3214.87 h60
  text "X" at 11764.71,3214.87 h60
  text "1MIL" at 11901.71,3214.87 h60
  text "OTHER" at 12398.71,3214.87 h60
  text "BOARD FINISH:" at 10339.71,3055.87 h60
  text "SILKSCREEN:" at 10494.94,2937.87 h60
  text "X" at 11443.71,2937.87 h60
  text "TOP" at 11569.71,2937.87 h60
  text "X" at 11953.71,2937.87 h60
  text "BOTTOM" at 12080.71,2937.87 h60
  text "SILKSCREEN COLOR:" at 10494.94,2770.87 h60
  text "X" at 11442.67,2770.87 h60
  text "WHITE" at 11569.71,2770.87 h60
  text "OTHER" at 12080.71,2770.87 h60
  text "SOLDER RESIST COLOR:" at 10494.94,2600.87 h60
  text "X" at 12167.68,2446.67 h60
  text "GREEN" at 11189.71,2441.67 h60
  text "BLUE" at 11780.71,2441.67 h60
  text "OTHER" at 12318.71,2441.67 h60
  text "RED" at 12708.71,2436.67 h60
  text "IMMERSION GOLD (ENIG)" at 11400.71,2253.15 h60
  text "ENEPIG" at 12738.25,2249.87 h60
  text "SURFACE FINISH:" at 10339.71,2248.87 h60
  text "X" at 11213.77,2248.87 h60
  text "IMM. TIN/SILVER OR EQUIV" at 10669.25,2091.87 h60
  text "OTHER" at 12100.71,2091.87 h60
  text "ARRAY/PANEL:" at 10339.71,1912.87 h60
  text "CUT AND TRIM PER MECH LAYER 1" at 11400.72,1908.58 h60
  text "N.C. ROUTE" at 11400.71,1756.87 h60
  text "X" at 12079.71,1756.87 h60
  text "V. SCORE" at 12266.71,1756.87 h60
  text "CERTIFICATION:" at 10339.71,1619.87 h60
  text "MATERIALS AND WORKMANSHIP FOR ALL PCBS" at 11064.71,1619.87 h60
  text "TO MEET OR EXCEED THE REQUIREMENTS OF:" at 11064.71,1521.87 h60
  text "X" at 10691.22,1385.36 h60
  text "ANSI IPC-A-600F CLASS ->" at 10830.22,1385.36 h60
  text "X" at 12469.27,1385.36 h60
  text "2" at 12588.22,1385.36 h60
  text "1" at 12273.22,1383.87 h60
  text "3" at 12942.22,1383.87 h60
  text "X" at 10693.27,1225.87 h60
  text "UL 94V-0" at 10830.22,1225.87 h60
  text "X" at 11505.27,1225.87 h60
  text "RoHS" at 11642.22,1225.87 h60
  text "OTHER" at 12286.62,1225.87 h60
  text "PER ORDER" at 12683.68,1225.87 h60
  text "ADDITIONAL REQUIREMENTS:" at 10339.71,1084.87 h60
  text "X" at 12321.27,985.87 h60
  text "YES" at 12457.22,983.87 h60
  text "NO" at 12911.22,983.87 h60
  text "VIA TENTING:" at 11561.79,978.79 h60
  text "MICROSECTION:" at 10414.48,969.87 h60
  text "YES" at 11320.22,969.87 h60
  text "REQUIRED" at 12181.71,813.72 h60
  text "BARE BOARD ELEC. TEST:" at 10414.48,810.87 h60
  text "NONE" at 11720.22,810.87 h60
  text "X" at 12054.71,810.87 h60
  text "PER ORDER" at 12773.71,810.87 h60
  text "MANUFACTURER'S UL:" at 10414.48,653.87 h60
  text "RAIL" at 11580.22,649.58 h60
  text "METAL" at 12072.03,649.58 h60
  text "SILK" at 12583.71,649.58 h60
  text "X" at 12447.25,649.23 h60
M11 Gerber Information:
  lines w10: -1284.75,-1230.94 5315.25,-1230.94 ; -1284.75,-1027.6 5317.25,-1027.6 ; -1284.75,-824.27 -1284.75,-1434.27 2720.25,-1434.27 5317.25,-1434.27 5317.25,-824.27 -1284.25,-824.27 -1284.25,-1434.27 291.25,-1434.27 ; 1180.25,-1434.27 1180.25,-824.27 ; 2447.25,-1027.6 2447.25,-824.27 ; 3287.25,-1027.6 3287.25,-824.27 ; 3909.25,-1440.77 3909.25,-1237.94
  text "ALL ARTWORK VIEWED FROM TOP SIDE" at -1221.25,-956.44 h60
  text "BOARD #:" at 1255.25,-956.44 h60
  text ".PRJ_Number" at 1800.75,-956.44 h60
  text "REV:" at 2645.25,-956.44 h60
  text ".PCB_Rev" at 2936.75,-956.44 h60
  text "SVN REV:" at 3483.25,-956.44 h60
  text ".VersionControl_RevNumber" at 3989.25,-956.44 h60
  text "LAYER NAME =" at -1221.25,-1159.26 h60
  text ".plot_File_Name" at -532.75,-1350.77 h60
  text "PLOT NAME =" at -1221.25,-1365.11 h60
  text "GENERATED    :" at 1257.25,-1365.11 h60
  text ".Print_Date" at 2126.75,-1365.11 h60
  text ".Print_Time" at 2855.75,-1365.11 h60
  text "TEXAS INSTRUMENTS" at 4120.25,-1365.11 h60
M12 Stackup:
  lines w1: 2970.79,3817.79 3000.79,3967.79 2940.79,3967.79 2970.79,3815.78 ; 2970.79,4487.79 2970.79,3815.78 ; 2970.79,4807.79 2970.79,5435.78 ; 4025.81,3815.78 2970.79,3815.78 ; 4040.81,5435.78 2970.79,5435.78 ; 2970.79,5435.78 3000.79,5297.79 2940.79,5297.79 2970.79,5435.78
  lines w6: -788.21,6722.79 9086.79,6722.79 ; 439.79,6427.79 439.79,7022.79 ; 2544.79,6422.79 2544.79,7022.79 ; 4599.79,6427.79 4599.79,7022.79 ; 6844.79,6427.79 6844.79,7022.79 ; 9086.79,6427.79 -788.21,6427.79 -788.21,7022.79 9089.79,7022.79 9089.79,6427.79
  lines w10: 4100.81,3615.78 4175.81,3615.78 ; 4140.81,5610.78 4215.81,5610.78 ; 4225.81,3615.78 4300.81,3615.78 ; 4265.81,5610.78 4340.81,5610.78 ; 4350.81,3615.78 4425.81,3615.78 ; 4390.81,5610.78 4465.81,5610.78 ; 4475.81,3615.78 4550.81,3615.78 ; 4515.81,5610.78 4590.81,5610.78 ; 4600.81,3615.78 4675.81,3615.78 ; 4640.81,5610.78 4715.81,5610.78 ; 4750.81,3615.78 4825.81,3615.78 ; 4765.81,5610.78 4840.81,5610.78 ; 4875.81,3615.78 4950.81,3615.78 ; 4890.81,5610.78 4965.81,5610.78 ; 5000.81,3615.78 5075.81,3615.78 ; 5015.81,5610.78 5090.81,5610.78 ; 5125.81,3615.78 5200.81,3615.78 ; 5140.81,5610.78 5215.81,5610.78 ; 5250.81,3615.78 5325.81,3615.78 ; 5265.81,5610.78 5340.81,5610.78 ; 5375.81,3615.78 5450.81,3615.78 ; 5390.81,5610.78 5465.81,5610.78 ; 5500.81,3615.78 5575.81,3615.78 ; 5515.81,5610.78 5590.81,5610.78 ; 4125.81,3815.78 4125.81,3865.78 5575.81,3865.78 5575.81,3815.78 4125.81,3815.78 ; 4125.81,4015.78 4125.81,4065.78 5575.81,4065.78 5575.81,4015.78 4125.81,4015.78 ; 4125.81,4165.78 4125.81,4315.78 5575.81,4315.78 5575.81,4165.78 4125.81,4165.78 ; 4125.81,4415.78 4125.81,4465.78 5575.81,4465.78 5575.81,4415.78 4125.81,4415.78 ; 4140.81,4535.78 4140.81,4685.78 5590.81,4685.78 5590.81,4535.78 4140.81,4535.78 ; 4140.81,4785.78 4140.81,4835.78 5590.81,4835.78 5590.81,4785.78 4140.81,4785.78 ; 4140.81,4935.78 4140.81,5085.78 5590.81,5085.78 5590.81,4935.78 4140.81,4935.78 ; 4140.81,5185.78 4140.81,5235.78 5590.81,5235.78 5590.81,5185.78 4140.81,5185.78 ; 4140.81,5385.78 4140.81,5435.78 5590.81,5435.78 5590.81,5385.78 4140.81,5385.78
  text "IMPEDANCE TABLE" at 1801.4,7173.2 h125
  text "REFERENCE GND" at 7209.79,6819.45 h70
  text "SPACING" at 2671.29,6806.12 h70
  text "IMPEDANCE +/- 10%" at 4703.29,6806.12 h70
  text "LAYER NO" at -685.71,6801.12 h70
  text "CONDUCTOR WIDTH" at 606.29,6796.12 h70
  text "GND" at 7649.79,6529.45 h70
  text "15 mil" at 3220.29,6521.12 h70
  text "50 OHMS" at 5453.29,6521.12 h70
  text "18.0 MIL" at 1208.29,6511.12 h70
  text "1" at -659.71,6506.12 h70
  text "4-LAYER STACK BUILD" at 3552.79,5975.79 h125
  text "PRIMARY SIDE, SILK SCREEN" at 5700.81,5550.78 h125
  text "SOLDER MASK(RED)------------->0.025 mm" at 5700.81,5355.78 h125
  text "TOP                    ----->0.035 mm" at 5700.81,5155.78 h125
  text "DIELECTRIC              ----->0.255 mm" at 5693.74,4975.51 h125
  text "GND                   ----->0.035 mm" at 5705.81,4760.78 h125
  text "1.4 mm+/-10%" at 2242.29,4616.12 h125
  text "DIELECTRIC              ----->0.7   mm" at 5709.34,4578.8 h125
  text "PWR                   ----->0.035 mm" at 5690.81,4390.78 h125
  text "DIELECTRIC              ----->0.255 mm" at 5690.81,4190.78 h125
  text "BOTTOM                 ----->0.035 mm" at 5695.81,3990.78 h125
  text "SOLDER MASK(RED)------------->0.025 mm" at 5680.81,3785.78 h125
  text "SECONDARY SIDE, SILK SCREEN" at 5680.81,3560.78 h125
Drill Drawing:
  rectangle: -992.75,-575.77 -867.75,-450.77
  rectangle: -867.75,-700.77 -492.75,-575.77
  lines w7: -992.75,-575.77 7.25,-575.77 ; -867.75,-700.77 -867.75,-450.77 ; -742.75,-700.77 -742.75,-450.77 ; -492.75,-700.77 -492.75,-450.77 ; -242.75,-700.77 -242.75,-450.77 ; -992.75,-700.77 -992.75,-450.77 7.25,-450.77 7.25,-700.77 -992.75,-700.77
  lines w15: 3149.29,1041.94 10117.38,1041.94 ; 3149.29,3291.94 10117.38,3291.94 ; 3700.16,891.94 3700.16,3441.94 ; 4397.98,891.94 4397.98,3441.94 ; 5743.58,891.94 5743.58,3441.94 ; 6249.46,891.94 6249.46,3441.94 ; 6983.26,891.94 6983.26,3441.94 ; 8124.93,891.94 8124.93,3441.94 ; 9338.58,891.94 9338.58,3441.94 ; 3149.29,891.94 10117.38,891.94 10117.38,3441.94 3149.29,3441.94 3149.29,891.94
  text "Symbol" at 3239.29,3336.94 h72
  text "Hit Count" at 3745.16,3336.94 h72
  text "Finished Hole Size" at 4442.98,3336.94 h72
  text "Plated" at 5788.58,3336.94 h72
  text "Hole Type" at 6294.46,3336.94 h72
  text "Physical Length" at 7028.26,3336.94 h72
  text "Rout Path Length" at 8169.93,3336.94 h72
  text "Tolerance" at 9383.58,3336.94 h72
  text "344" at 3745.16,3186.94 h60
  text "8.00mil (0.203mm)" at 4442.98,3186.94 h60
  text "PTH" at 5788.58,3186.94 h60
  text "Round" at 6294.46,3186.94 h60
  text "-" at 7028.26,3186.94 h60
  text "-" at 8169.93,3186.94 h60
  text "O" at 3210.2,3176.95 h66.67
  text "244" at 3745.16,3036.94 h60
  text "12.00mil (0.305mm)" at 4442.98,3036.94 h60
  text "PTH" at 5788.58,3036.94 h60
  text "Round" at 6294.46,3036.94 h60
  text "-" at 7028.26,3036.94 h60
  text "-" at 8169.93,3036.94 h60
  text "P" at 3210.2,3026.95 h66.67
  text "38" at 3745.16,2886.94 h60
  text "12.10mil (0.307mm)" at 4442.98,2886.94 h60
  text "PTH" at 5788.58,2886.94 h60
  text "Round" at 6294.46,2886.94 h60
  text "-" at 7028.26,2886.94 h60
  text "-" at 8169.93,2886.94 h60
  text "M" at 3210.2,2876.95 h66.67
  text "18" at 3745.16,2736.94 h60
  text "16.00mil (0.406mm)" at 4442.98,2736.94 h60
  text "PTH" at 5788.58,2736.94 h60
  text "Round" at 6294.46,2736.94 h60
  text "-" at 7028.26,2736.94 h60
  text "-" at 8169.93,2736.94 h60
  text "N" at 3210.2,2726.95 h66.67
  text "2" at 3745.16,2586.94 h60
  text "23.62mil (0.600mm)" at 4442.98,2586.94 h60
  text "PTH" at 5788.58,2586.94 h60
  text "Slot" at 6294.46,2586.94 h60
  text "51.18mil (1.300mm)" at 7028.26,2586.94 h60
  text "27.56mil (0.700mm)" at 8169.93,2586.94 h60
  text "J" at 3210.2,2576.95 h66.67
  text "20" at 3745.16,2436.94 h60
  text "27.95mil (0.710mm)" at 4442.98,2436.94 h60
  text "PTH" at 5788.58,2436.94 h60
  text "Round" at 6294.46,2436.94 h60
  text "-" at 7028.26,2436.94 h60
  text "-" at 8169.93,2436.94 h60
  text "I" at 3221.3,2426.95 h66.67
  text "2" at 3745.16,2286.94 h60
  text "33.46mil (0.850mm)" at 4442.98,2286.94 h60
  text "PTH" at 5788.58,2286.94 h60
  text "Round" at 6294.46,2286.94 h60
  text "-" at 7028.26,2286.94 h60
  text "-" at 8169.93,2286.94 h60
  text "K" at 3210.2,2276.95 h66.67
  text "1" at 3745.16,2136.94 h60
  text "37.99mil (0.965mm)" at 4442.98,2136.94 h60
  text "PTH" at 5788.58,2136.94 h60
  text "Round" at 6294.46,2136.94 h60
  text "-" at 7028.26,2136.94 h60
  text "-" at 8169.93,2136.94 h60
  text "D" at 3210.2,2126.95 h66.67
  text "6" at 3745.16,1986.94 h60
  text "39.00mil (0.991mm)" at 4442.98,1986.94 h60
  text "NPTH" at 5788.58,1986.94 h60
  text "Round" at 6294.46,1986.94 h60
  text "-" at 7028.26,1986.94 h60
  text "-" at 8169.93,1986.94 h60
  text "E" at 3210.2,1976.95 h66.67
  text "2" at 3745.16,1836.94 h60
  text "39.37mil (1.000mm)" at 4442.98,1836.94 h60
  text "NPTH" at 5788.58,1836.94 h60
  text "Round" at 6294.46,1836.94 h60
  text "-" at 7028.26,1836.94 h60
  text "-" at 8169.93,1836.94 h60
  text "H" at 3210.2,1826.95 h66.67
  text "6" at 3745.16,1686.94 h60
  text "39.37mil (1.000mm)" at 4442.98,1686.94 h60
  text "PTH" at 5788.58,1686.94 h60
  text "Round" at 6294.46,1686.94 h60
  text "-" at 7028.26,1686.94 h60
  text "-" at 8169.93,1686.94 h60
  text "F" at 3210.2,1676.95 h66.67
  text "6" at 3745.16,1536.94 h60
  text "43.31mil (1.100mm)" at 4442.98,1536.94 h60
  text "PTH" at 5788.58,1536.94 h60
  text "Round" at 6294.46,1536.94 h60
  text "-" at 7028.26,1536.94 h60
  text "-" at 8169.93,1536.94 h60
  text "C" at 3210.2,1526.95 h66.67
  text "82" at 3745.16,1386.94 h60
  text "45.28mil (1.150mm)" at 4442.98,1386.94 h60
  text "PTH" at 5788.58,1386.94 h60
  text "Round" at 6294.46,1386.94 h60
  text "-" at 7028.26,1386.94 h60
  text "-" at 8169.93,1386.94 h60
  text "B" at 3210.2,1376.95 h66.67
  text "6" at 3745.16,1236.94 h60
  text "51.18mil (1.300mm)" at 4442.98,1236.94 h60
  text "PTH" at 5788.58,1236.94 h60
  text "Round" at 6294.46,1236.94 h60
  text "-" at 7028.26,1236.94 h60
  text "-" at 8169.93,1236.94 h60
  text "G" at 3210.2,1226.95 h66.67
  text "4" at 3745.16,1086.94 h60
  text "98.43mil (2.500mm)" at 4442.98,1086.94 h60
  text "NPTH" at 5788.58,1086.94 h60
  text "Round" at 6294.46,1086.94 h60
  text "-" at 7028.26,1086.94 h60
  text "-" at 8169.93,1086.94 h60
  text "L" at 3210.2,1076.95 h66.67
  text "781 Total" at 3745.16,936.94 h60
  text "Slot definitions :" at 3239.29,791.97 h60
  text "Rout Path Length" at 4271.98,791.97 h60
  text "= Calculated from tool start centre position to tool end centre position." at 5254.68,791.97 h60
  text "Physical Length" at 4271.98,691.99 h60
  text "= Rout Path Length + Tool Size = Slot length as defined in the PCB layout" at 5194.7,691.99 h60
  text "ADDITIONAL FAB NOTES" at 3117.59,407.89 h100
  text "1.8 MIL,12MIL &16 MIL VIAS ARE TENTED ON BOTH SIDES." at 3137.09,154.79 h100
  text "2.ALL OTHER DRILL TOLERANCE FOR PLATED +/-3 MIL AND NPTH +/-2 MIL" at 3133.62,-64.85 h100
  text "(UNLESS OTHERWISE SPECIFIED)" at 3262.18,-317.65 h100
  text ".layer_Name" at -237.21,-1145.21 h60

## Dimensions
0,0 to -176,0 on M2 Board Dimensions
2163.79,2373.79 to 2200.79,2373.79 on M2 Board Dimensions
-312.46,1935.38 to -201.21,1910 on M2 Board Dimensions
2120.79,-99.21 to 2200.79,1796.79 on M2 Board Dimensions
2120.79,-99.21 to 2120.79,3958.79 on M2 Board Dimensions
2120.79,-99.21 to 2163.79,2279.79 on M2 Board Dimensions
2120.79,-99.21 to 2200.79,2073.97 on M2 Board Dimensions
2200.79,2373.79 to 2120.79,-99.21 on M2 Board Dimensions
2120.79,-19.21 to 2343.79,-136.21 on M2 Board Dimensions
-992.75,-700.77 to 7.25,-700.77 on Drill Drawing
-99.21,3878.79 to 2200.79,3878.79 on M2 Board Dimensions
0,0 to -99.21,-19.21 on M2 Board Dimensions
0,3849.57 to -19.21,3958.79 on M2 Board Dimensions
